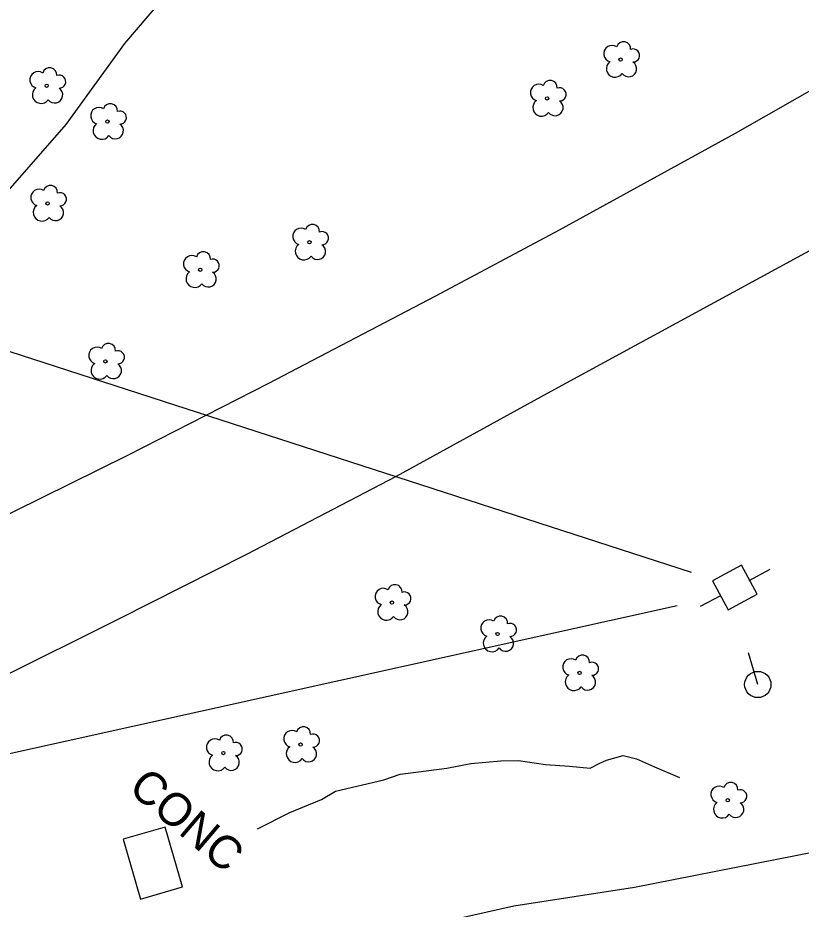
# Model space of a CAD drawing. Extents: x 2076109 to 2080761, y 592812 to 596750.
# Drawn here: x 2076837.6 to 2076956.7, y 595468.6 to 595604.1 of the extents above; entities that cross this region are included whole.
import ezdxf

# ---------------------------------------------------------------- set-up
doc = ezdxf.new("R2010")
doc.units = 0
for name, color, linetype in [('RD_EX_Conc', 7, 'Continuous'), ('RD_EX_Conc_txCode', 7, 'Continuous'), ('RD_EX_H2O', 7, 'Continuous'), ('RD_EX_Road', 7, 'Continuous'), ('RD_EX_UT', 7, 'Continuous'), ('RD_EX_VEG', 7, 'Continuous')]:
    doc.layers.add(name, color=color, linetype=linetype)

msp = doc.modelspace()

# ---------------------------------------------------------------- linework, layer by layer
at = {"layer": 'RD_EX_Conc'}
msp.add_lwpolyline([(2076856.28, 595470.15), (2076862.69, 595472.02), (2076860.05, 595481.1), (2076853.64, 595479.24)], close=True, dxfattribs=at)
msp.add_lwpolyline([(2076856.28, 595470.15), (2076862.69, 595472.02), (2076860.05, 595481.1), (2076853.64, 595479.24)], close=True, dxfattribs=at)
at = {"layer": 'RD_EX_H2O'}
for points in [[(2076953.18, 595787.61), (2076953.11, 595768.11), (2076952.56, 595756.13), (2076952.64, 595748.41), (2076952.76, 595745.08), (2076953.8, 595742.99), (2076953.36, 595730.22), (2076953.03, 595725.71), (2076951.39, 595721.38), (2076949.37, 595718.3), (2076942.5, 595711.04), (2076932.67, 595698.19), (2076918.85, 595680.89), (2076905.91, 595664.86), (2076891.97, 595647.71), (2076883.67, 595637.84), (2076877.03, 595627.21), (2076865.95, 595614.44), (2076853.87, 595600.18), (2076844.92, 595587.87), (2076832.87, 595574.13), (2076822.92, 595563.08), (2076804.28, 595545.77)], [(2076953.18, 595787.61), (2076953.11, 595768.11), (2076952.56, 595756.13), (2076952.64, 595748.41), (2076952.76, 595745.08), (2076953.8, 595742.99), (2076953.36, 595730.22), (2076953.03, 595725.71), (2076951.39, 595721.38), (2076949.37, 595718.3), (2076942.5, 595711.04), (2076932.67, 595698.19), (2076918.85, 595680.89), (2076905.91, 595664.86), (2076891.97, 595647.71), (2076883.67, 595637.84), (2076877.03, 595627.21), (2076865.95, 595614.44), (2076853.87, 595600.18), (2076844.92, 595587.87), (2076832.87, 595574.13), (2076822.92, 595563.08), (2076804.28, 595545.77)], [(2076874.08, 595480.84), (2076878.97, 595483.28), (2076883.77, 595485.29), (2076885.93, 595486.54), (2076893.25, 595488.25), (2076895.72, 595489.15), (2076898.53, 595489.48), (2076902.83, 595490.02), (2076906.45, 595490.77), (2076911.01, 595491.18), (2076913.72, 595491.23), (2076917.83, 595490.59), (2076921.49, 595490.34), (2076924.61, 595490.04), (2076925.95, 595490.75), (2076927.08, 595491.26), (2076929.64, 595491.95), (2076931.67, 595491.46), (2076934.39, 595490.26), (2076938.16, 595488.62)], [(2076874.08, 595480.84), (2076878.97, 595483.28), (2076883.77, 595485.29), (2076885.93, 595486.54), (2076893.25, 595488.25), (2076895.72, 595489.15), (2076898.53, 595489.48), (2076902.83, 595490.02), (2076906.45, 595490.77), (2076911.01, 595491.18), (2076913.72, 595491.23), (2076917.83, 595490.59), (2076921.49, 595490.34), (2076924.61, 595490.04), (2076925.95, 595490.75), (2076927.08, 595491.26), (2076929.64, 595491.95), (2076931.67, 595491.46), (2076934.39, 595490.26), (2076938.16, 595488.62)]]:
    msp.add_lwpolyline(points, dxfattribs=at)
at = {"layer": 'RD_EX_Road'}
for points in [[(2076707.59, 595470.49), (2076721.43, 595476.47), (2076750.6, 595488.97), (2076774.96, 595499.94), (2076798.62, 595510.68), (2076813.13, 595517.44), (2076832.67, 595526.92), (2076854.37, 595537.63), (2076875.76, 595548.58), (2076901.14, 595561.82), (2076919.96, 595571.87), (2076946.71, 595586.58), (2076970.23, 595599.97)], [(2076707.59, 595470.49), (2076721.43, 595476.47), (2076750.6, 595488.97), (2076774.96, 595499.94), (2076798.62, 595510.68), (2076813.13, 595517.44), (2076832.67, 595526.92), (2076854.37, 595537.63), (2076875.76, 595548.58), (2076901.14, 595561.82), (2076919.96, 595571.87), (2076946.71, 595586.58), (2076970.23, 595599.97)], [(2076787.98, 595465.96), (2076787.69, 595469.85), (2076788.12, 595473.87), (2076788.92, 595476.83), (2076790, 595478.96), (2076791.35, 595481.36), (2076792.92, 595483.16), (2076794.83, 595484.81), (2076800.92, 595487.89), (2076818.52, 595496.12), (2076834.57, 595503.55), (2076852.99, 595512.75), (2076872.44, 595522.55), (2076895.16, 595534.41), (2076918.14, 595547.06), (2076946.45, 595562.46), (2076964.21, 595572.12)], [(2076787.98, 595465.96), (2076787.69, 595469.85), (2076788.12, 595473.87), (2076788.92, 595476.83), (2076790, 595478.96), (2076791.35, 595481.36), (2076792.92, 595483.16), (2076794.83, 595484.81), (2076800.92, 595487.89), (2076818.52, 595496.12), (2076834.57, 595503.55), (2076852.99, 595512.75), (2076872.44, 595522.55), (2076895.16, 595534.41), (2076918.14, 595547.06), (2076946.45, 595562.46), (2076964.21, 595572.12)], [(2076958.9, 595477.35), (2076931.35, 595471.91), (2076913.01, 595469.05), (2076892.76, 595464.5)], [(2076958.9, 595477.35), (2076931.35, 595471.91), (2076913.01, 595469.05), (2076892.76, 595464.5)]]:
    msp.add_lwpolyline(points, dxfattribs=at)
at = {"layer": 'RD_EX_UT'}
for p, q in [((2076812.76, 595561.03), (2076939.97, 595519.83)), ((2076812.76, 595561.03), (2076939.97, 595519.83)), ((2076947.62, 595520.88), (2076943.21, 595518.53)), ((2076947.62, 595520.88), (2076943.21, 595518.53)), ((2076949.97, 595516.47), (2076947.62, 595520.88)), ((2076949.97, 595516.47), (2076947.62, 595520.88)), ((2076948.76, 595518.59), (2076951.98, 595520.3)), ((2076948.76, 595518.59), (2076951.98, 595520.3)), ((2076943.21, 595518.53), (2076945.56, 595514.12)), ((2076943.21, 595518.53), (2076945.56, 595514.12)), ((2076945.56, 595514.12), (2076949.97, 595516.47)), ((2076945.56, 595514.12), (2076949.97, 595516.47)), ((2076941.39, 595514.66), (2076944.45, 595516.29)), ((2076941.39, 595514.66), (2076944.45, 595516.29)), ((2076566.44, 595432.36), (2076937.84, 595514.77)), ((2076566.44, 595432.36), (2076937.84, 595514.77)), ((2076950.08, 595502.76), (2076948.66, 595507.55)), ((2076950.08, 595502.76), (2076948.66, 595507.55))]:
    msp.add_line(p, q, dxfattribs=at)
msp.add_circle((2076950.08, 595502.76), 2, dxfattribs=at)
msp.add_circle((2076950.08, 595502.76), 2, dxfattribs=at)
at = {"layer": 'RD_EX_VEG'}
for centre in [(2076929.23, 595597.76), (2076929.23, 595597.76), (2076842.03, 595593.77), (2076842.03, 595593.77), (2076918.06, 595591.84), (2076918.06, 595591.84), (2076851.25, 595588.33), (2076851.25, 595588.33), (2076842.16, 595575.89), (2076842.16, 595575.89), (2076881.96, 595569.99), (2076881.96, 595569.99), (2076865.37, 595565.81), (2076865.37, 595565.81), (2076850.95, 595551.88), (2076850.95, 595551.88), (2076894.49, 595515.22), (2076894.49, 595515.22), (2076910.53, 595510.44), (2076910.53, 595510.44), (2076922.99, 595504.53), (2076922.99, 595504.53), (2076880.6, 595493.62), (2076880.6, 595493.62), (2076868.87, 595492.34), (2076868.87, 595492.34), (2076945.51, 595485.16), (2076945.51, 595485.16)]:
    msp.add_circle(centre, 0.25, dxfattribs=at)
for centre, radius, start, end in [((2076929.68, 595599.4), 1.08, 354.6037, 164.3834), ((2076929.68, 595599.4), 1.08, 354.6037, 164.3834), ((2076927.94, 595598.65), 1.26, 56.0792, 254.3614), ((2076927.94, 595598.65), 1.26, 56.0792, 254.3614), ((2076931.13, 595598.38), 0.995, 268.39, 111.6741), ((2076931.13, 595598.38), 0.995, 268.39, 111.6741), ((2076842.48, 595595.42), 1.08, 354.6037, 164.3834), ((2076842.48, 595595.42), 1.08, 354.6037, 164.3834), ((2076928.38, 595596.38), 1.32, 126.51, 325.3863), ((2076928.38, 595596.38), 1.32, 126.51, 325.3863), ((2076930.45, 595596.35), 1.22, 216.1941, 57.732), ((2076930.45, 595596.35), 1.22, 216.1941, 57.732), ((2076840.74, 595594.66), 1.26, 56.0792, 254.3614), ((2076840.74, 595594.66), 1.26, 56.0792, 254.3614), ((2076843.93, 595594.39), 0.995, 268.39, 111.6741), ((2076843.93, 595594.39), 0.995, 268.39, 111.6741), ((2076916.77, 595592.74), 1.26, 56.0792, 254.3614), ((2076916.77, 595592.74), 1.26, 56.0792, 254.3614), ((2076918.51, 595593.49), 1.08, 354.6037, 164.3834), ((2076918.51, 595593.49), 1.08, 354.6037, 164.3834), ((2076841.18, 595592.4), 1.32, 126.51, 325.3863), ((2076841.18, 595592.4), 1.32, 126.51, 325.3863), ((2076843.25, 595592.37), 1.22, 216.1941, 57.732), ((2076843.25, 595592.37), 1.22, 216.1941, 57.732), ((2076919.96, 595592.46), 0.995, 268.39, 111.6741), ((2076919.96, 595592.46), 0.995, 268.39, 111.6741), ((2076851.7, 595589.97), 1.08, 354.6037, 164.3834), ((2076851.7, 595589.97), 1.08, 354.6037, 164.3834), ((2076917.21, 595590.47), 1.32, 126.51, 325.3863), ((2076917.21, 595590.47), 1.32, 126.51, 325.3863), ((2076919.28, 595590.44), 1.22, 216.1941, 57.732), ((2076919.28, 595590.44), 1.22, 216.1941, 57.732), ((2076849.96, 595589.22), 1.26, 56.0792, 254.3614), ((2076849.96, 595589.22), 1.26, 56.0792, 254.3614), ((2076853.15, 595588.94), 0.995, 268.39, 111.6741), ((2076853.15, 595588.94), 0.995, 268.39, 111.6741), ((2076850.4, 595586.95), 1.32, 126.51, 325.3863), ((2076850.4, 595586.95), 1.32, 126.51, 325.3863), ((2076852.47, 595586.92), 1.22, 216.1941, 57.732), ((2076852.47, 595586.92), 1.22, 216.1941, 57.732), ((2076840.86, 595576.79), 1.26, 56.0792, 254.3614), ((2076840.86, 595576.79), 1.26, 56.0792, 254.3614), ((2076842.61, 595577.54), 1.08, 354.6037, 164.3834), ((2076842.61, 595577.54), 1.08, 354.6037, 164.3834), ((2076844.05, 595576.51), 0.995, 268.39, 111.6741), ((2076844.05, 595576.51), 0.995, 268.39, 111.6741), ((2076841.31, 595574.52), 1.32, 126.51, 325.3863), ((2076841.31, 595574.52), 1.32, 126.51, 325.3863), ((2076843.38, 595574.49), 1.22, 216.1941, 57.732), ((2076843.38, 595574.49), 1.22, 216.1941, 57.732), ((2076880.67, 595570.88), 1.26, 56.0792, 254.3614), ((2076880.67, 595570.88), 1.26, 56.0792, 254.3614), ((2076882.41, 595571.63), 1.08, 354.6037, 164.3834), ((2076882.41, 595571.63), 1.08, 354.6037, 164.3834), ((2076883.86, 595570.61), 0.995, 268.39, 111.6741), ((2076883.86, 595570.61), 0.995, 268.39, 111.6741), ((2076881.11, 595568.61), 1.32, 126.51, 325.3863), ((2076881.11, 595568.61), 1.32, 126.51, 325.3863), ((2076883.18, 595568.58), 1.22, 216.1941, 57.732), ((2076883.18, 595568.58), 1.22, 216.1941, 57.732), ((2076864.08, 595566.7), 1.26, 56.0792, 254.3614), ((2076864.08, 595566.7), 1.26, 56.0792, 254.3614), ((2076865.83, 595567.45), 1.08, 354.6037, 164.3834), ((2076865.83, 595567.45), 1.08, 354.6037, 164.3834), ((2076867.27, 595566.42), 0.995, 268.39, 111.6741), ((2076867.27, 595566.42), 0.995, 268.39, 111.6741), ((2076864.53, 595564.43), 1.32, 126.51, 325.3863), ((2076864.53, 595564.43), 1.32, 126.51, 325.3863), ((2076866.59, 595564.4), 1.22, 216.1941, 57.732), ((2076866.59, 595564.4), 1.22, 216.1941, 57.732), ((2076851.4, 595553.52), 1.08, 354.6037, 164.3834), ((2076851.4, 595553.52), 1.08, 354.6037, 164.3834), ((2076849.66, 595552.77), 1.26, 56.0792, 254.3614), ((2076849.66, 595552.77), 1.26, 56.0792, 254.3614), ((2076852.85, 595552.5), 0.995, 268.39, 111.6741), ((2076852.85, 595552.5), 0.995, 268.39, 111.6741), ((2076850.1, 595550.5), 1.32, 126.51, 325.3863), ((2076850.1, 595550.5), 1.32, 126.51, 325.3863), ((2076852.17, 595550.47), 1.22, 216.1941, 57.732), ((2076852.17, 595550.47), 1.22, 216.1941, 57.732), ((2076894.95, 595516.87), 1.08, 354.6037, 164.3834), ((2076894.95, 595516.87), 1.08, 354.6037, 164.3834), ((2076893.2, 595516.12), 1.26, 56.0792, 254.3614), ((2076893.2, 595516.12), 1.26, 56.0792, 254.3614), ((2076896.39, 595515.84), 0.995, 268.39, 111.6741), ((2076896.39, 595515.84), 0.995, 268.39, 111.6741), ((2076893.65, 595513.85), 1.32, 126.51, 325.3863), ((2076893.65, 595513.85), 1.32, 126.51, 325.3863), ((2076895.71, 595513.82), 1.22, 216.1941, 57.732), ((2076895.71, 595513.82), 1.22, 216.1941, 57.732), ((2076909.24, 595511.33), 1.26, 56.0792, 254.3614), ((2076909.24, 595511.33), 1.26, 56.0792, 254.3614), ((2076910.99, 595512.08), 1.08, 354.6037, 164.3834), ((2076910.99, 595512.08), 1.08, 354.6037, 164.3834), ((2076912.43, 595511.06), 0.995, 268.39, 111.6741), ((2076912.43, 595511.06), 0.995, 268.39, 111.6741), ((2076909.69, 595509.06), 1.32, 126.51, 325.3863), ((2076909.69, 595509.06), 1.32, 126.51, 325.3863), ((2076911.75, 595509.03), 1.22, 216.1941, 57.732), ((2076911.75, 595509.03), 1.22, 216.1941, 57.732), ((2076923.44, 595506.17), 1.08, 354.6037, 164.3834), ((2076923.44, 595506.17), 1.08, 354.6037, 164.3834), ((2076921.7, 595505.42), 1.26, 56.0792, 254.3614), ((2076921.7, 595505.42), 1.26, 56.0792, 254.3614), ((2076924.89, 595505.15), 0.995, 268.39, 111.6741), ((2076924.89, 595505.15), 0.995, 268.39, 111.6741), ((2076922.14, 595503.15), 1.32, 126.51, 325.3863), ((2076922.14, 595503.15), 1.32, 126.51, 325.3863), ((2076924.21, 595503.12), 1.22, 216.1941, 57.732), ((2076924.21, 595503.12), 1.22, 216.1941, 57.732), ((2076881.05, 595495.27), 1.08, 354.6037, 164.3834), ((2076881.05, 595495.27), 1.08, 354.6037, 164.3834), ((2076869.32, 595493.98), 1.08, 354.6037, 164.3834), ((2076869.32, 595493.98), 1.08, 354.6037, 164.3834), ((2076879.31, 595494.51), 1.26, 56.0792, 254.3614), ((2076879.31, 595494.51), 1.26, 56.0792, 254.3614), ((2076882.5, 595494.24), 0.995, 268.39, 111.6741), ((2076882.5, 595494.24), 0.995, 268.39, 111.6741), ((2076867.57, 595493.23), 1.26, 56.0792, 254.3614), ((2076867.57, 595493.23), 1.26, 56.0792, 254.3614), ((2076870.76, 595492.95), 0.995, 268.39, 111.6741), ((2076870.76, 595492.95), 0.995, 268.39, 111.6741), ((2076868.02, 595490.96), 1.32, 126.51, 325.3863), ((2076868.02, 595490.96), 1.32, 126.51, 325.3863), ((2076879.75, 595492.24), 1.32, 126.51, 325.3863), ((2076879.75, 595492.24), 1.32, 126.51, 325.3863), ((2076881.82, 595492.22), 1.22, 216.1941, 57.732), ((2076881.82, 595492.22), 1.22, 216.1941, 57.732), ((2076870.09, 595490.93), 1.22, 216.1941, 57.732), ((2076870.09, 595490.93), 1.22, 216.1941, 57.732), ((2076944.21, 595486.06), 1.26, 56.0792, 254.3614), ((2076944.21, 595486.06), 1.26, 56.0792, 254.3614), ((2076945.96, 595486.81), 1.08, 354.6037, 164.3834), ((2076945.96, 595486.81), 1.08, 354.6037, 164.3834), ((2076947.41, 595485.78), 0.995, 268.39, 111.6741), ((2076947.41, 595485.78), 0.995, 268.39, 111.6741), ((2076944.66, 595483.79), 1.32, 126.51, 325.3863), ((2076944.66, 595483.79), 1.32, 126.51, 325.3863), ((2076946.73, 595483.76), 1.22, 216.1941, 57.732), ((2076946.73, 595483.76), 1.22, 216.1941, 57.732)]:
    msp.add_arc(centre, radius, start, end, dxfattribs=at)

# ---------------------------------------------------------------- texts
at = {"layer": 'RD_EX_Conc_txCode'}
msp.add_text('CONC', height=5, rotation=319.6274, dxfattribs=at).set_placement((2076854.24, 595486.68))
msp.add_text('CONC', height=5, rotation=319.6274, dxfattribs=at).set_placement((2076854.24, 595486.68))

doc.saveas('drawing.dxf')
